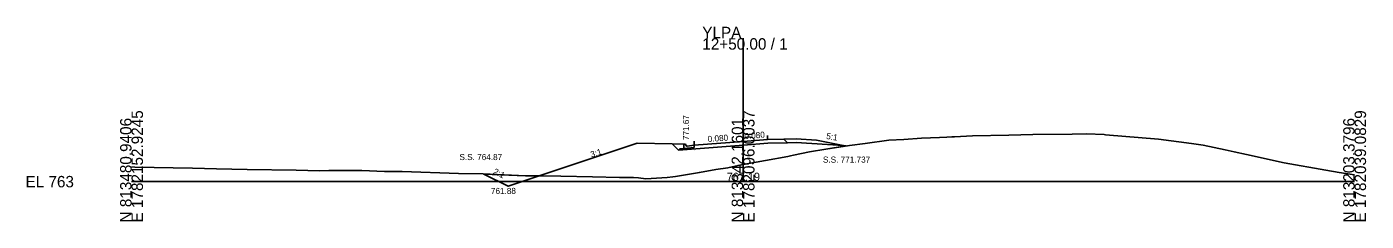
# Model space of a CAD drawing. Extents: x -76 to 1303, y -10 to 9544.
# Drawn here: x -25.7 to 302.8, y 2490.3 to 2537.9 of the extents above; entities that cross this region are included whole.
import ezdxf

# ---------------------------------------------------------------- set-up
doc = ezdxf.new("R2010")
doc.units = 0
for name, color, linetype in [('Exist Cross Section Cell', 7, 'Continuous'), ('Exist XS Center Line Elevation Label', 7, 'Continuous'), ('Exist XS Ground Line', 7, 'Continuous'), ('Prop XS Ditch Slope Text', 7, 'Continuous'), ('Prop XS Ditch Standard Text', 7, 'Continuous'), ('Prop XS Dump Level', 7, 'Continuous'), ('Prop XS Earthwork Shape', 7, 'Continuous'), ('Prop XS EOT Tick Mark', 7, 'Continuous'), ('Prop XS Finish Grade', 7, 'Continuous'), ('Prop XS Finish Grade CurbGutter', 7, 'Continuous'), ('Prop XS Finish Grade Earthwork', 7, 'Continuous'), ('Prop XS Finish Grade Paved Shoulder', 7, 'Continuous'), ('Prop XS Finish Grade Pavement', 7, 'Continuous'), ('Prop XS Hydro Elevations', 7, 'Continuous'), ('Prop XS Pvmt Edge Slope', 7, 'Continuous'), ('Prop XS SE Text', 7, 'Continuous'), ('Prop XS Side Slope Text', 7, 'Continuous'), ('Prop XS SS Elevation Text', 7, 'Continuous'), ('Prop XS Subgrade CurbGutter', 7, 'Continuous'), ('Prop XS Subgrade Earthwork', 7, 'Continuous'), ('Scratch_Level_3', 7, 'Continuous')]:
    doc.layers.add(name, color=color, linetype=linetype)

msp = doc.modelspace()

# ---------------------------------------------------------------- linework, layer by layer
at = {"layer": 'Exist Cross Section Cell'}
for p, q in [((150, 2500), (150, 2535.15)), ((0, 2500), (150, 2500)), ((150, 2500), (300, 2500))]:
    msp.add_line(p, q, dxfattribs=at)
at = {"layer": 'Exist XS Ground Line'}
for p, q in [((179.93, 2509.35), (185.75, 2510.16)), ((185.75, 2510.16), (189.42, 2510.35)), ((189.42, 2510.35), (193.78, 2510.63)), ((193.78, 2510.63), (198.17, 2510.84)), ((198.17, 2510.84), (199.97, 2510.9)), ((199.97, 2510.9), (201.22, 2510.97)), ((201.22, 2510.97), (201.88, 2511)), ((201.88, 2511), (206.25, 2511.19)), ((206.25, 2511.19), (215.2, 2511.41)), ((215.2, 2511.41), (221.09, 2511.55)), ((221.09, 2511.55), (230.73, 2511.67)), ((230.73, 2511.67), (234.2, 2511.72)), ((234.2, 2511.72), (238.57, 2511.54)), ((238.57, 2511.54), (238.92, 2511.51)), ((238.92, 2511.51), (251.89, 2510.42)), ((251.89, 2510.42), (259.98, 2509.37)), ((162.34, 2506.46), (166.31, 2507.33)), ((166.31, 2507.33), (170.27, 2507.97)), ((170.27, 2507.97), (176.13, 2508.87)), ((176.13, 2508.87), (179.93, 2509.35)), ((259.98, 2509.37), (262.84, 2508.98)), ((262.84, 2508.98), (268.23, 2507.81)), ((268.23, 2507.81), (270.45, 2507.33)), ((270.45, 2507.33), (273.49, 2506.64)), ((0, 2503.59), (0.78, 2503.57)), ((0.78, 2503.57), (14.96, 2503.33)), ((146.28, 2503.42), (148.79, 2503.97)), ((148.79, 2503.97), (150, 2504.19)), ((150, 2504.19), (160.95, 2506.18)), ((160.95, 2506.18), (161.59, 2506.3)), ((161.59, 2506.3), (162.34, 2506.46)), ((273.49, 2506.64), (282.7, 2504.59)), ((282.7, 2504.59), (292.93, 2502.83)), ((14.96, 2503.33), (20.81, 2503.14)), ((20.81, 2503.14), (28.35, 2503)), ((28.35, 2503), (40.4, 2502.82)), ((40.4, 2502.82), (46.13, 2502.67)), ((46.13, 2502.67), (48.43, 2502.71)), ((48.43, 2502.71), (56.45, 2502.72)), ((56.45, 2502.72), (62.02, 2502.5)), ((62.02, 2502.5), (66.38, 2502.46)), ((66.38, 2502.46), (80.18, 2502.02)), ((80.18, 2502.02), (86.25, 2501.88)), ((86.25, 2501.88), (96.62, 2501.44)), ((96.62, 2501.44), (105.28, 2501.33)), ((105.28, 2501.33), (113.08, 2501.2)), ((113.08, 2501.2), (119.65, 2501.04)), ((119.65, 2501.04), (123.11, 2501.02)), ((123.11, 2501.02), (124.33, 2500.91)), ((124.33, 2500.91), (126.17, 2500.66)), ((126.17, 2500.66), (131.36, 2501.04)), ((131.36, 2501.04), (132.75, 2501.15)), ((132.75, 2501.15), (133.39, 2501.23)), ((133.39, 2501.23), (139.28, 2502.27)), ((139.28, 2502.27), (143.34, 2502.98)), ((143.34, 2502.98), (146.28, 2503.42)), ((292.93, 2502.83), (296.23, 2502.27)), ((296.23, 2502.27), (300, 2501.67))]:
    msp.add_line(p, q, dxfattribs=at)
at = {"layer": 'Prop XS Dump Level'}
for p, q in [((150, 2509.87), (156, 2510.35)), ((138, 2508.91), (150, 2509.87))]:
    msp.add_line(p, q, dxfattribs=at)
at = {"layer": 'Prop XS Earthwork Shape'}
for points in [[(162.98, 2509.57), (174.56, 2508.88), (175.26, 2508.74), (170.27, 2507.97), (166.31, 2507.33), (162.34, 2506.46), (161.59, 2506.3), (160.95, 2506.18), (150, 2504.19), (148.79, 2503.97), (146.28, 2503.42), (143.34, 2502.98), (139.28, 2502.27), (133.39, 2501.23), (132.75, 2501.15), (131.36, 2501.04), (126.17, 2500.66), (124.33, 2500.91), (123.11, 2501.02), (119.65, 2501.04), (113.08, 2501.2), (105.28, 2501.33), (99.96, 2501.4), (124, 2509.41), (132.61, 2509.23), (134.16, 2507.68), (150.07, 2508.96), (156.05, 2509.43), (160.9, 2509.53)], [(99.96, 2501.4), (92.4, 2498.88), (86.42, 2501.87), (96.62, 2501.44)]]:
    msp.add_lwpolyline(points, close=True, dxfattribs=at)
at = {"layer": 'Prop XS EOT Tick Mark'}
for p, q in [((156, 2510.35), (156, 2511.35)), ((138, 2508.91), (138, 2509.91))]:
    msp.add_line(p, q, dxfattribs=at)
at = {"layer": 'Prop XS Finish Grade'}
for p, q in [((160, 2510.43), (163, 2510.49)), ((163, 2510.49), (168, 2510.19)), ((168, 2510.19), (174.56, 2508.88)), ((135.5, 2509.17), (132.61, 2509.23))]:
    msp.add_line(p, q, dxfattribs=at)
at = {"layer": 'Prop XS Finish Grade CurbGutter'}
for p, q in [((135.5, 2509.17), (135.75, 2509.17)), ((135.75, 2509.17), (135.88, 2509.16)), ((135.97, 2509.06), (135.88, 2509.16)), ((136.03, 2508.81), (135.97, 2509.06)), ((136.13, 2508.72), (136.03, 2508.81)), ((136.25, 2508.7), (136.13, 2508.72)), ((138, 2508.91), (136.25, 2508.7))]:
    msp.add_line(p, q, dxfattribs=at)
at = {"layer": 'Prop XS Finish Grade Earthwork'}
for p, q in [((124, 2509.41), (92.4, 2498.88)), ((132.61, 2509.23), (124, 2509.41)), ((175.26, 2508.74), (174.56, 2508.88)), ((92.4, 2498.88), (86.42, 2501.87))]:
    msp.add_line(p, q, dxfattribs=at)
at = {"layer": 'Prop XS Finish Grade Paved Shoulder'}
msp.add_line((156, 2510.35), (160, 2510.43), dxfattribs=at)
at = {"layer": 'Prop XS Finish Grade Pavement'}
for p, q in [((150, 2509.87), (156, 2510.35)), ((138, 2508.91), (150, 2509.87))]:
    msp.add_line(p, q, dxfattribs=at)
at = {"layer": 'Prop XS Pvmt Edge Slope'}
for p, q in [((160, 2510.43), (160.9, 2509.53)), ((134.5, 2508.05), (134.16, 2507.68)), ((135.5, 2508.13), (134.5, 2508.05))]:
    msp.add_line(p, q, dxfattribs=at)
at = {"layer": 'Prop XS Subgrade CurbGutter'}
for p, q in [((135.5, 2508.13), (135.5, 2509.17)), ((138, 2508.33), (135.5, 2508.13)), ((138, 2508.91), (138, 2508.33))]:
    msp.add_line(p, q, dxfattribs=at)
at = {"layer": 'Prop XS Subgrade Earthwork'}
for p, q in [((134.16, 2507.68), (132.61, 2509.23)), ((134.16, 2507.68), (150.07, 2508.96)), ((138, 2507.66), (138, 2507.66)), ((150.07, 2508.96), (156.05, 2509.43)), ((156.05, 2509.43), (160.9, 2509.53)), ((160.9, 2509.53), (162.98, 2509.57)), ((162.98, 2509.57), (174.56, 2508.88))]:
    msp.add_line(p, q, dxfattribs=at)
at = {"layer": 'Scratch_Level_3'}
for p, q in [((163, 2510.49), (160, 2510.43)), ((160, 2510.43), (160.9, 2509.53)), ((168, 2510.19), (163, 2510.49)), ((174.56, 2508.88), (168, 2510.19)), ((160.9, 2509.53), (162.98, 2509.57)), ((162.98, 2509.57), (174.56, 2508.88))]:
    msp.add_line(p, q, dxfattribs=at)

# ---------------------------------------------------------------- texts
at = {"layer": 'Exist Cross Section Cell'}
for s, p in [('YLPA', (140, 2535.15)), ('12+50.00 / 1', (140, 2532.35)), ('EL 763', (-26, 2498.6))]:
    msp.add_text(s, height=2.8, dxfattribs=at).set_placement(p)
for s, p in [('E 1782152.9245', (2.8, 2490)), ('E 1782096.0037', (152.8, 2490)), ('E 1782039.0829', (302.8, 2490)), ('N 813480.9406', (0, 2490)), ('N 813342.1601', (150, 2490)), ('N 813203.3796', (300, 2490))]:
    msp.add_text(s, height=2.8, rotation=90, dxfattribs=at).set_placement(p)
at = {"layer": 'Exist XS Center Line Elevation Label'}
msp.add_text('767.19', height=2, dxfattribs=at).set_placement((145.97, 2500.19))
at = {"layer": 'Prop XS Ditch Slope Text'}
msp.add_text('5:1', height=1.5, rotation=350.5377, dxfattribs=at).set_placement((170.31, 2510.49))
at = {"layer": 'Prop XS Ditch Standard Text'}
msp.add_text('761.88', height=1.5, dxfattribs=at).set_placement((88.15, 2496.97))
at = {"layer": 'Prop XS Dump Level'}
msp.add_text('Case4', height=0.04, dxfattribs=at).set_placement((168, 2510.15))
at = {"layer": 'Prop XS Hydro Elevations'}
msp.add_text('771.67', height=1.5, rotation=90, dxfattribs=at).set_placement((136.75, 2510.17))
at = {"layer": 'Prop XS SE Text'}
for p in [(141.38, 2509.68), (150.38, 2510.4)]:
    msp.add_text('0.080', height=1.5, rotation=4.5739, dxfattribs=at).set_placement(p)
at = {"layer": 'Prop XS Side Slope Text'}
for s, rotation, p in [('3:1', 17.1748, (112.82, 2505.89)), ('2:1', 333.4349, (88.58, 2502))]:
    msp.add_text(s, height=1.5, rotation=rotation, dxfattribs=at).set_placement(p)
at = {"layer": 'Prop XS SS Elevation Text'}
for s, p in [('S.S. 764.87', (80.43, 2505.28)), ('S.S. 771.737', (169.58, 2504.65))]:
    msp.add_text(s, height=1.5, dxfattribs=at).set_placement(p)

doc.saveas('drawing.dxf')
